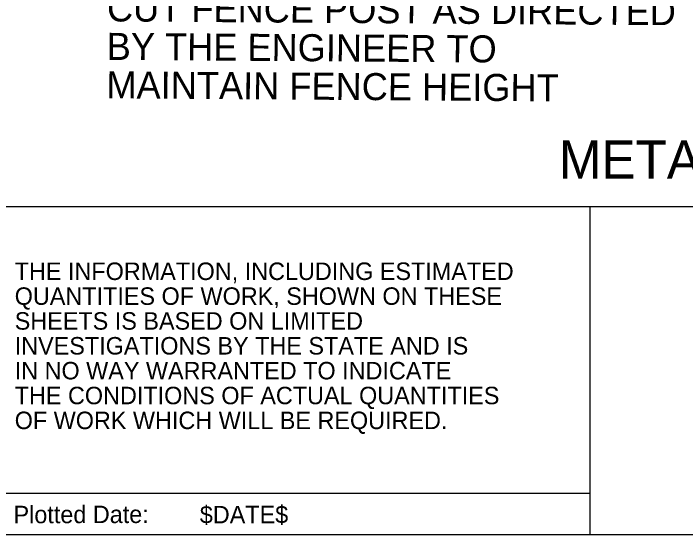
# Model space of a CAD drawing. Extents: x 0 to 1270, y 0 to 830.
# Drawn here: x 239.1 to 362.1, y 0 to 95.4 of the extents above; entities that cross this region are included whole.
import ezdxf

# ---------------------------------------------------------------- set-up
doc = ezdxf.new("R2010")
doc.units = 0
for name, color, linetype in [('CT_Border_Perimeter_Shape', 7, 'Continuous'), ('CT_CSHT_GeneralLabel', 7, 'Continuous'), ('CT_Dimensions', 7, 'Continuous'), ('CT_Disclaimer_Text', 7, 'Continuous'), ('CT_Title_Block_Linework', 7, 'Continuous'), ('CT_Title_Block_Text', 7, 'Continuous')]:
    doc.layers.add(name, color=color, linetype=linetype)

# ---------------------------------------------------------------- blocks, each defined once
blk = doc.blocks.new('BDR_CTDOT_Standards')
at = {"layer": 'CT_Border_Perimeter_Shape'}
blk.add_lwpolyline([(0, 0), (1270, 0), (1270, 830), (0, 830)], close=True, dxfattribs=at)
at = {"layer": 'CT_Title_Block_Linework'}
for p, q in [((1270, 60), (0, 60)), ((344.55, 60), (344.55, 0)), ((344.55, 60), (344.55, 0)), ((344.55, 7.5), (0, 7.5))]:
    blk.add_line(p, q, dxfattribs=at)
at = {"layer": 'CT_Disclaimer_Text'}
for s, p in [('THE INFORMATION, INCLUDING ESTIMATED ', (239.35, 46.59)), ('QUANTITIES OF WORK, SHOWN ON THESE ', (239.35, 42.04)), ('SHEETS IS BASED ON LIMITED ', (239.35, 37.5)), ('INVESTIGATIONS BY THE STATE AND IS', (239.35, 32.95)), ('IN NO WAY WARRANTED TO INDICATE ', (239.35, 28.4)), ('THE CONDITIONS OF ACTUAL QUANTITIES ', (239.35, 23.85)), ('OF WORK WHICH WILL BE REQUIRED.', (239.35, 19.3))]:
    blk.add_text(s, height=3.2, dxfattribs=at).set_placement(p)
at = {"layer": 'CT_Title_Block_Text'}
for s, p in [('Plotted Date:', (239.14, 2.06)), ('$DATE$', (273.22, 2.04))]:
    blk.add_text(s, height=3.2, rotation=0.125, dxfattribs=at).set_placement(p)

msp = doc.modelspace()

# ---------------------------------------------------------------- block references
at = {"layer": 'CT_Title_Block_Text'}
msp.add_blockref('BDR_CTDOT_Standards', (0, 0), dxfattribs=at)

# ---------------------------------------------------------------- texts
at = {"layer": 'CT_CSHT_GeneralLabel'}
msp.add_text('METAL POST IN ROCK', height=7, dxfattribs=at).set_placement((338.9, 65.14))
at = {"layer": 'CT_Dimensions'}
for s, p in [('CUT FENCE POST AS DIRECTED', (256.22, 93.92)), ('BY THE ENGINEER TO', (256.17, 86.88)), ('MAINTAIN FENCE HEIGHT', (256.12, 79.84))]:
    msp.add_text(s, height=4.95, rotation=359.6101, dxfattribs=at).set_placement(p)

doc.saveas('drawing.dxf')
